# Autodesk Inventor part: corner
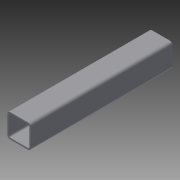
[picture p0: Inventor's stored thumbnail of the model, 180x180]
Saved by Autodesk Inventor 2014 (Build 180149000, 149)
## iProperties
Created: 2008-04
Part Number: corner
Document SubType Name: Modeling
Designer: Jayson Martinez
Density: 1 g/cm^3
Material: Generic
Appearance: Default
Author: Jayson Martinez
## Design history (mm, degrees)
sketch "Sketch1"
  geometry: L1 (6.35, 0)-(44.45, 0); L2 (50.8, 6.35)-(50.8, 44.45); L3 (44.45, 50.8)-(6.35, 50.8); L4 (0, 44.45)-(0, 6.35); L5 (3.175, 6.35)-(3.175, 44.45); L6 (6.35, 47.625)-(44.45, 47.625); L7 (47.625, 44.45)-(47.625, 6.35); L8 (44.45, 3.175)-(6.35, 3.175); A1 r 6.35 centre (6.35, 44.45) between (6.35, 50.8) and (0, 44.45); A2 r 6.35 centre (6.35, 6.35) between (0, 6.35) and (6.35, 0); A3 r 6.35 centre (44.45, 6.35) between (44.45, 0) and (50.8, 6.35); A4 r 6.35 centre (44.45, 44.45) between (50.8, 44.45) and (44.45, 50.8); A5 r 3.175 centre (6.35, 44.45) between (6.35, 47.625) and (3.175, 44.45); A6 r 3.175 centre (44.45, 44.45) between (47.625, 44.45) and (44.45, 47.625); A7 r 3.175 centre (44.45, 6.35) between (44.45, 3.175) and (47.625, 6.35); A8 r 3.175 centre (6.35, 6.35) between (3.175, 6.35) and (6.35, 3.175); 3 further points
  constraints: 16 end point, 16 point on circle, 8 centre point, 8 tangent, 6 point on line, 4 parallel, 3 equal radius, 2 perpendicular, 1 horizontal, 7 other
  dimensions: "d0" = 50.8 distance of point (0, 0) point (50.8, 0) (= MemberWidth); "d1" = 50.8 distance of point (0, 50.8) point (0, 0) (= MemberWidth); "d2" = 6.35 radius of A1 (= 2 x MemberThickness); "d3" = 3.175 distance between parallel lines of L4 L5 (= MemberThickness)
extrude "Extrusion1" new body sketch "Sketch1" distance "d4" = 304.8 (= CornerLength); taper "d5" = 0 deg
body "Solid1"
other parameters: "MemberThickness" = 3.175, "MemberWidth" = 50.8, "CornerLength" = 304.8
